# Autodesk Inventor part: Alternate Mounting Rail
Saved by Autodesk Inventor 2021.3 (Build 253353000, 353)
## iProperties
Created: 2023-01
Part Number: Alternate Mounting Rail
Material: Generic
Document SubType Name: Modeling
Designer: AdminForWorker
Density: 1 g/cm^3
Appearance: Default
Title: Alternate Mounting Rail
Author: AdminForWorker
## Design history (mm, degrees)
feature "Mounting Shoe"
feature "Mounting Rail 100x10mm"
body "Solid1"
body "Solid2"
